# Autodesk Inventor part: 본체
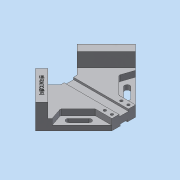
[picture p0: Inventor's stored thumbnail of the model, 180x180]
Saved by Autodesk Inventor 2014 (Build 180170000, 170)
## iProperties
Created: 2019-04
Part Number: 본체
Material: 알루미늄 6061
Document SubType Name: Modeling
Designer: 601-06
Density: 2.71 g/cm^3
Appearance: 알루미늄 - 평지
Mass: 603.629 g
Surface Area: 426.622 cm^2
Volume: 222.741 cm^3
Author: 601-06
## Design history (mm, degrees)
sketch "스케치4"
  geometry: L1 (-20, 0)-(0, 0); L2 (149.706, 0)-(114.35, -35.355); L3 (64.853, -84.853)-(0, -20); L4 (0, 0)-(0, -20); L5 (114.35, -35.355)-(93, -14.005); L6 (93, -14.005)-(93, 0); L7 (0, -20)-(-20, 0); L8 (114.35, -35.355)-(64.853, -84.853); L9 (93, 0)-(149.706, 0); L10 (0, 0)-(93, 0); L11 (93, 14.005)-(93, 0); L12 (114.35, 35.355)-(93, 14.005); L13 (114.35, 35.355)-(64.853, 84.853); L14 (64.853, 84.853)-(0, 20); L15 (0, 0)-(0, 20); 2 further points
  constraints: 30 end point, 12 perpendicular, 4 symmetric about line, 3 coincident, 3 horizontal
  dimensions: "d1" = 120 distance of L3.start L1.start; "d2" = 120 distance of L2.start L3.start; "d3" = 20 distance from line of L4 L1.start; "d5" = 93 distance between parallel lines of L4 L6; "d6" = 70 distance between parallel lines of L3 L5
extrude "돌출1" new body sketch "스케치4" distance "d7" = 18; taper "d8" = 0 deg
sketch "스케치5"
  geometry: L1 (-93, -14.005)-(-114.35, -35.355) reference; L2 (-114.35, -35.355)-(-64.853, -84.853) reference; L3 (-64.853, -84.853)-(0, -20) reference; L4 (0, 20)-(-64.853, 84.853) reference; L5 (-64.853, 84.853)-(-114.35, 35.355) reference; L6 (-114.35, 35.355)-(-93, 14.005) reference; L7 (-54.246, -74.246)-(-103.744, -24.749); L8 (-103.744, 24.749)-(-54.246, 74.246); 1 further point
  constraints: 4 end point, 4 point on line, 2 perpendicular
  dimensions: "d9" = 15 distance between parallel lines of L5 L8; "d10" = 15 distance between parallel lines of L2 L7
extrude "돌출2" join sketch "스케치5" distance "d11" = 24; taper "d12" = 0 deg
sketch "스케치6"
  geometry: L1 (-54.246, -74.246)-(0, -20) reference; L2 (0, -20)-(0, 20) reference; L3 (-93, 14.005)-(-93, -14.005) reference; L4 (-28.284, -20)-(-57.782, -49.497); L5 (-57.782, -49.497)-(-50.711, -70.711); L6 (0, -20)-(-28.284, -20); L7 (-114.35, -35.355)-(-64.853, -84.853) reference; 1 further point
  constraints: 6 end point, 2 point on line, 1 parallel, 1 perpendicular
  dimensions: "d13" = 20 distance between parallel lines of L4 L1; "d14" = 20 distance of L5.end L7.end; "d15" = 30 distance from line of L7 L4.end; "d16" = 20 distance from line of point (0, 0) L6
extrude "돌출3" cut sketch "스케치6" distance "d17" = 10; taper "d18" = 0 deg
sketch "스케치7"
  geometry: L1 (0, -20)-(-50.711, -70.711) reference; L2 (-26.669, -32.527)-(-43.64, -49.497); L3 (-29.851, -29.345)-(-46.822, -46.315); L4 (-40.458, -52.679)-(-23.487, -35.709); L5 (-114.35, -35.355)-(-64.853, -84.853) reference; A1 r 4.5 centre (-26.669, -32.527) between (-23.487, -35.709) and (-29.851, -29.345); A2 r 4.5 centre (-43.64, -49.497) between (-46.822, -46.315) and (-40.458, -52.679); 2 further points
  constraints: 8 end point, 4 point on circle, 4 tangent, 2 centre point, 2 parallel, 1 midpoint
  dimensions: "d19" = 9 distance between parallel lines of L3 L4; "d20" = 40 distance from line of L5 L2.end; "d21" = 24 distance of L2.start L2.end; "d22" = 10 distance between parallel lines of L1 L2
extrude "돌출4" cut sketch "스케치7" stored distance "d23" = 10; taper "d24" = 0 deg
sketch "스케치8"
  geometry: L1 (0, -20)-(0, 20) reference; C1 r 2.25 at (-6, -14); C2 r 2.25 at (-18, -14); 1 further point
  constraints: 2 centre point
  dimensions: "d25" = 4.5 diameter of C1; "d26" = 14 vertical distance of point (0, 0) C1.centre; "d27" = 6 distance from line of C1.centre L1; "d28" = 4.5 diameter of C2; "d29" = 14 vertical distance of point (0, 0) C2.centre; "d30" = 12 distance of C2.centre C1.centre
extrude "돌출5" cut sketch "스케치8" stored distance "d31" = 10; taper "d32" = 0 deg
sketch "스케치9"
  geometry: C1 r 2.25 at (-6, 14) reference; C2 r 2.25 at (-18, 14) reference; 1 further point
hole "구멍1" sketch "스케치9" at (-18, 14), (-6, 14) diameter "d33" = 8; stored, may be unused: countersink angle "d37" = 90 deg, drill point angle "d39" = 0 deg; dims "d34" = 6, "d35" = 4, "d36" = 2, "d38" = 10
sketch "스케치10"
  geometry: L1 (0, -20)-(0, 20) reference; L2 (-93, 14.005)-(-93, -14.005) reference; L3 (-93, -8)-(0, -8); L4 (0, -8)-(0, 8); L5 (0, 8)-(-93, 8); L6 (-93, 8)-(-93, -8); 1 further point
  constraints: 8 end point, 2 parallel, 2 point on line, 1 horizontal, 1 perpendicular
  dimensions: "d40" = 16 distance between parallel lines of L3 L5; "d41" = 8 distance from line of L5 point (0, 0)
extrude "돌출6" cut sketch "스케치10" distance "d42" = 3.5; taper "d43" = 0 deg
sketch "스케치11"
  geometry: L1 (0, 20)-(0, -20) reference; L2 (-93, -14.005)-(-93, 14.005) reference; L3 (-93, 6)-(0, 6); L4 (0, 6)-(0, -6); L5 (0, -6)-(-93, -6); L6 (-93, -6)-(-93, 6); 1 further point
  constraints: 8 end point, 2 parallel, 2 point on line, 1 horizontal, 1 perpendicular
  dimensions: "d44" = 12 distance between parallel lines of L3 L5; "d45" = 6 distance from line of point (0, 0) L5
extrude "돌출7" cut sketch "스케치11" distance "d46" = 3; taper "d47" = 0 deg
sketch "스케치12"
  geometry: L1 (-114.35, -35.355)-(-64.853, -84.853) reference; L2 (-64.853, -84.853)-(-54.246, -74.246) reference; 2 further points
  constraints: 1 other
  dimensions: "d48" = 35 distance from line of L2 point (-84.298, -54.801); "d50" = 7.5 distance from line of L1 point (-84.298, -54.801)
feature "엠보싱1" sketch "스케치12" dims "d3" = 20, "d51" = 0.5, "d52" = 0
fillet "모깎기1" dims "d53" = 3
node "솔리드1"
mirror "대칭1"
mirror "대칭2"
